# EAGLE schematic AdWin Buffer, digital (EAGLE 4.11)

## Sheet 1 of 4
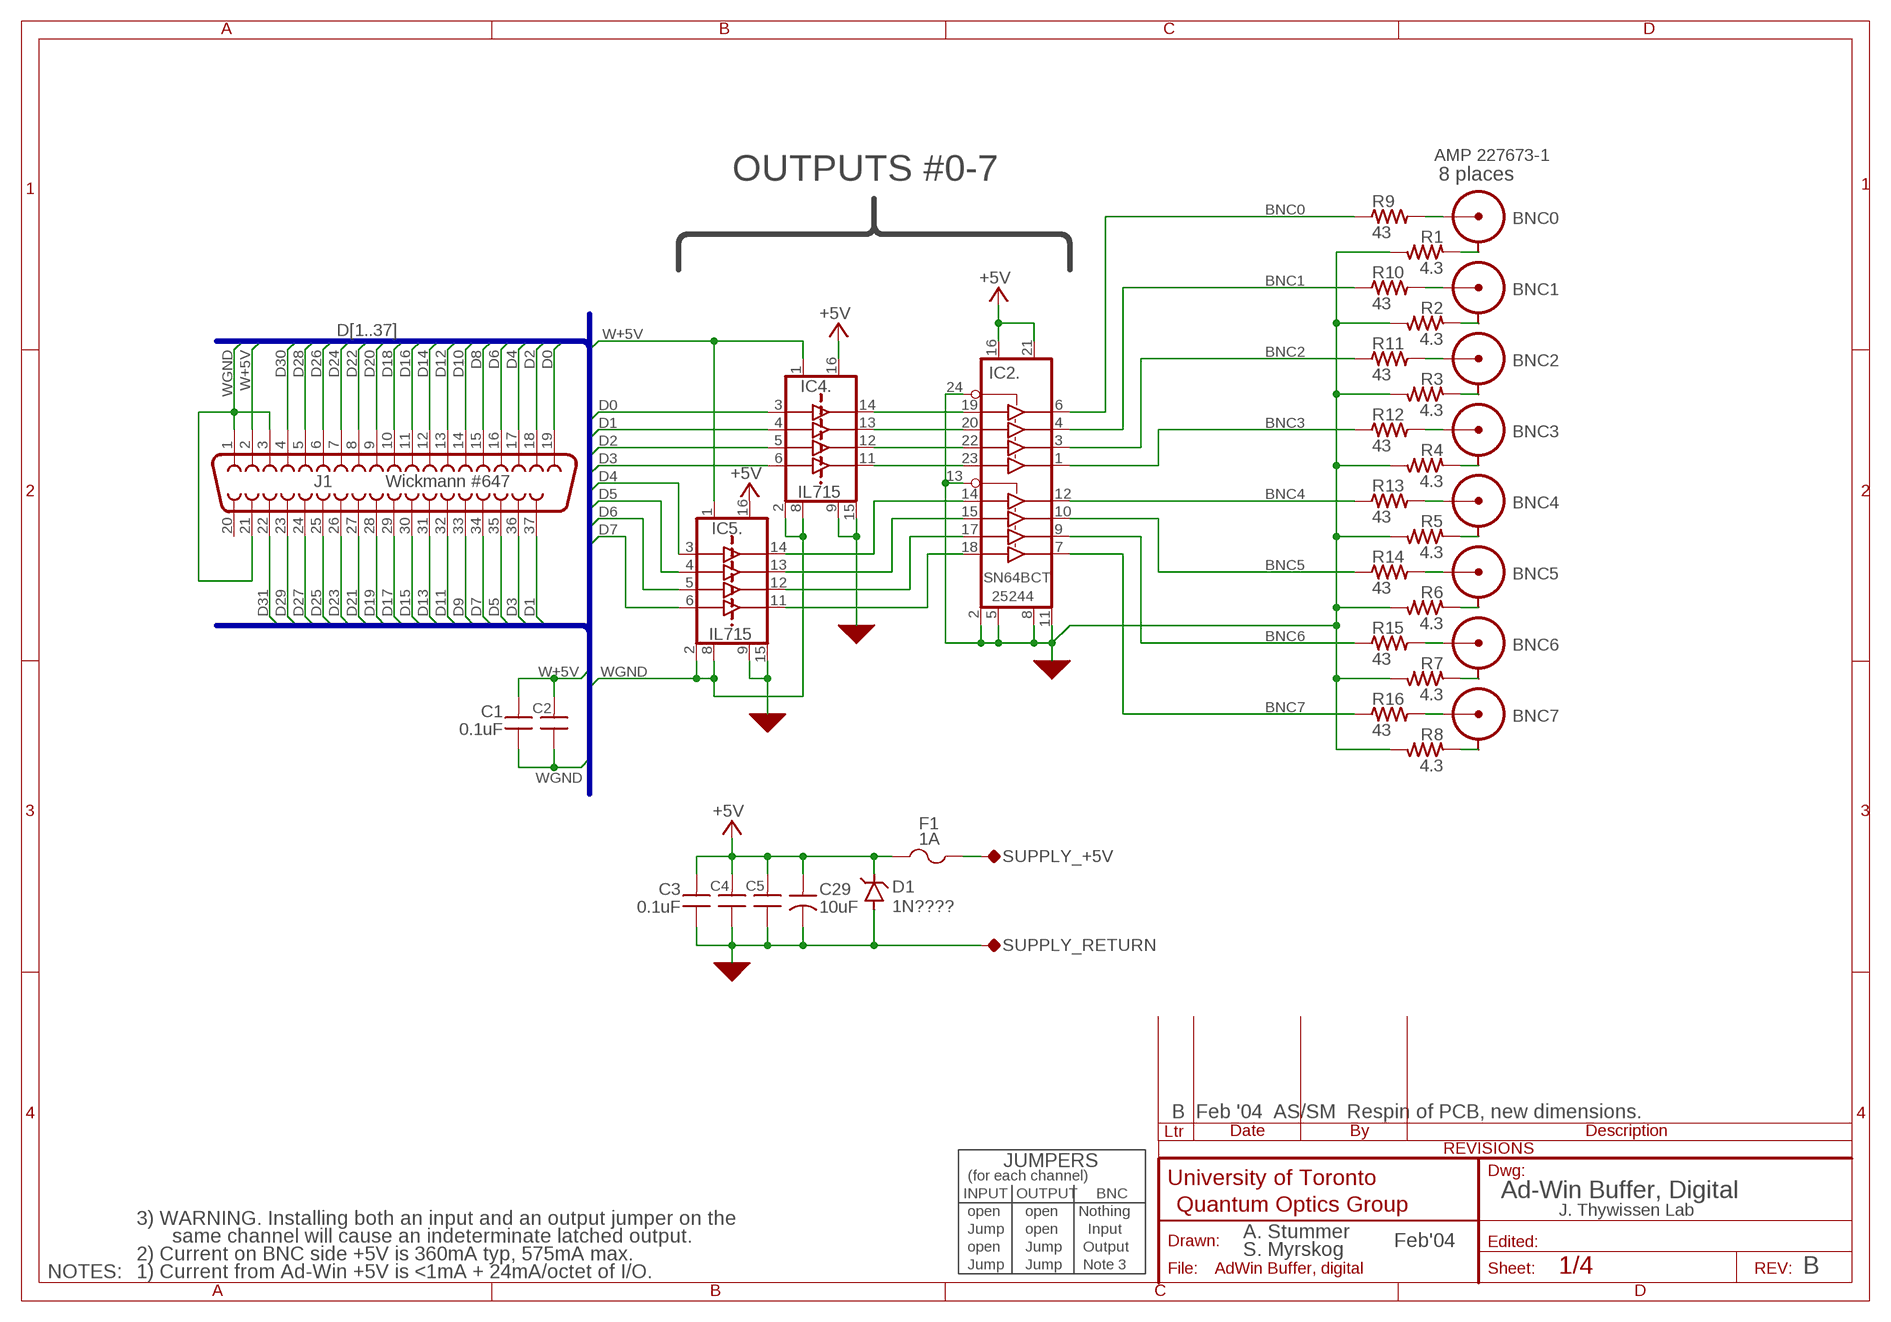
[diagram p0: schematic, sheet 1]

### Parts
BNC0  AMP 227673-1  CONN-BNC-AMPHENOL-PCB-TYPE1  [CONN-BNC-AMPHENOL-TYPE1]
BNC1  CONN-BNC-AMPHENOL-PCB-TYPE1  [CONN-BNC-AMPHENOL-TYPE1]
BNC2  CONN-BNC-AMPHENOL-PCB-TYPE1  [CONN-BNC-AMPHENOL-TYPE1]
BNC3  CONN-BNC-AMPHENOL-PCB-TYPE1  [CONN-BNC-AMPHENOL-TYPE1]
BNC4  CONN-BNC-AMPHENOL-PCB-TYPE1  [CONN-BNC-AMPHENOL-TYPE1]
BNC5  CONN-BNC-AMPHENOL-PCB-TYPE1  [CONN-BNC-AMPHENOL-TYPE1]
BNC6  CONN-BNC-AMPHENOL-PCB-TYPE1  [CONN-BNC-AMPHENOL-TYPE1]
BNC7  CONN-BNC-AMPHENOL-PCB-TYPE1  [CONN-BNC-AMPHENOL-TYPE1]
C1  0.1uF  CAP-V-0805  [0805]
C2  CAP-V-0805  [0805]
C3  0.1uF  CAP-V-0805  [0805]
C4  CAP-V-0805  [0805]
C5  CAP-V-0805  [0805]
C29  10uF  CAP-POL-EIA-B  [EIA-B]
D1  1N????  ZENER-EIA-B  [EIA-B]
F1  1A  FUSE5X20-2  [FUSE5X20-2]
IC2  64BCT25244NT  [DIL24]
IC4  IL715  [SOIC-16]
IC5  IL715  [SOIC-16]
J1  Wickmann #647  CONN-DB37V  [F37V]
R1  4.3  R-H-0805  [0805]
R2  4.3  R-H-0805  [0805]
R3  4.3  R-H-0805  [0805]
R4  4.3  R-H-0805  [0805]
R5  4.3  R-H-0805  [0805]
R6  4.3  R-H-0805  [0805]
R7  4.3  R-H-0805  [0805]
R8  4.3  R-H-0805  [0805]
R9  43  R-H-0805  [0805]
R10  43  R-H-0805  [0805]
R11  43  R-H-0805  [0805]
R12  43  R-H-0805  [0805]
R13  43  R-H-0805  [0805]
R14  43  R-H-0805  [0805]
R15  43  R-H-0805  [0805]
R16  43  R-H-0805  [0805]
SUPPLY_+5V  TP-HOLE-0.042  [TP-HOLE]
SUPPLY_RETURN  TP-HOLE-0.042  [TP-HOLE]

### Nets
+5V [Pwr/Gnd .025"w]: C3.2 C4.2 C5.2 C29.2(POS) D1.2(C) F1.1(1A) IC2.16(.:VDD1) IC2.21(.:VDD2) IC4.16(.:VDDOUT) IC5.16(.:VDDOUT) ; also sheet 2,3,4
AGND [Pwr/Gnd .025"w]: C3.1 C4.1 C5.1 C29.1(NEG) D1.1(A) IC2.2(.:COM1) IC2.5(.:COM2) IC2.8(.:COM3) IC2.11(.:COM4) IC2.13(.:EN-58) IC2.24(.:EN-14) IC4.9(.:COM1OUT) IC4.15(.:COM2OUT) IC5.9(.:COM1OUT) IC5.15(.:COM2OUT) R1.2 R2.2 R3.2 R4.2 R5.2 R6.2 R7.2 R8.2 SUPPLY_RETURN.P$1(TP) ; also sheet 2,3,4
BNC0: IC2.6(4:Q) R9.1
BNC1: IC2.4(3:Q) R10.1
BNC2: IC2.3(2:Q) R11.1
BNC3: IC2.1(1:Q) R12.1
BNC4: IC2.12(8:Q) R13.1
BNC5: IC2.10(7:Q) R14.1
BNC6: IC2.9(6:Q) R15.1
BNC7: IC2.7(5:Q) R16.1
D0: IC4.3(IN) J1.19
D1: IC4.4(IN) J1.37
D2: IC4.5(IN) J1.18
D3: IC4.6(IN) J1.36
D4: IC5.3(IN) J1.17
D5: IC5.4(IN) J1.35
D6: IC5.5(IN) J1.16
D7: IC5.6(IN) J1.34
D8: J1.15 ; also sheet 2
D9: J1.33 ; also sheet 2
D10: J1.14 ; also sheet 2
D11: J1.32 ; also sheet 2
D12: J1.13 ; also sheet 2
D13: J1.31 ; also sheet 2
D14: J1.12 ; also sheet 2
D15: J1.30 ; also sheet 2
D16: J1.11 ; also sheet 3
D17: J1.29 ; also sheet 3
D18: J1.10 ; also sheet 3
D19: J1.28 ; also sheet 3
D20: J1.9 ; also sheet 3
D21: J1.27 ; also sheet 3
D22: J1.8 ; also sheet 3
D23: J1.26 ; also sheet 3
D24: J1.7 ; also sheet 4
D25: J1.25 ; also sheet 4
D26: J1.6 ; also sheet 4
D27: J1.24 ; also sheet 4
D28: J1.5 ; also sheet 4
D29: J1.23 ; also sheet 4
D30: J1.4 ; also sheet 4
D31: J1.22 ; also sheet 4
N$1: IC2.19(4:IN) IC4.14(Q)
N$2: IC2.20(3:IN) IC4.13(Q)
N$3: IC2.22(2:IN) IC4.12(Q)
N$4: IC2.23(1:IN) IC4.11(Q)
N$7: IC2.18(5:IN) IC5.11(Q)
N$10: BNC0.CONDUCTOR R9.2
N$11: BNC1.CONDUCTOR R10.2
N$12: BNC2.CONDUCTOR R11.2
N$13: BNC3.CONDUCTOR R12.2
N$14: BNC4.CONDUCTOR R13.2
N$15: BNC5.CONDUCTOR R14.2
N$16: IC2.17(6:IN) IC5.12(Q)
N$17: IC2.15(7:IN) IC5.13(Q)
N$18: IC2.14(8:IN) IC5.14(Q)
N$19: BNC6.CONDUCTOR R15.2
N$20: BNC7.CONDUCTOR R16.2
N$24: BNC0.SHIELD R1.1
N$27: BNC1.SHIELD R2.1
N$28: BNC2.SHIELD R3.1
N$29: BNC3.SHIELD R4.1
N$37: BNC4.SHIELD R5.1
N$39: BNC5.SHIELD R6.1
N$40: BNC6.SHIELD R7.1
N$41: BNC7.SHIELD R8.1
N$49 [Pwr/Gnd .025"w]: F1.2(2A) SUPPLY_+5V.P$1(TP)
W+5V [Pwr/Gnd .025"w]: C1.2 C2.2 IC4.1(.:VDDIN) IC5.1(.:VDDIN) J1.2 ; also sheet 2,3,4
WGND [Pwr/Gnd .025"w]: C1.1 C2.1 IC4.2(.:COM1IN) IC4.8(.:COM2IN) IC5.2(.:COM1IN) IC5.8(.:COM2IN) J1.1 J1.3 J1.21 ; also sheet 2,3,4
Unconnected: J1.20

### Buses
D[1..37]

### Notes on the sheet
- OUTPUTS #0-7 | 8 places
- B  Feb '04  AS/SM  Respin of PCB, new dimensions.
- JUMPERS
- (for each channel)
- INPUT | OUTPUT | BNC | Ad-Win Buffer, Digital
- open | open | Nothing | J. Thywissen Lab
- 3) WARNING. Installing both an input and an output jumper on the
- Jump | open | Input
- same channel will cause an indeterminate latched output. | A. Stummer
- Feb'04
- open | Jump | Output
- 2) Current on BNC side +5V is 360mA typ, 575mA max. | S. Myrskog
- Jump | Jump | Note 3
- NOTES: | 1) Current from Ad-Win +5V is <1mA + 24mA/octet of I/O. | B

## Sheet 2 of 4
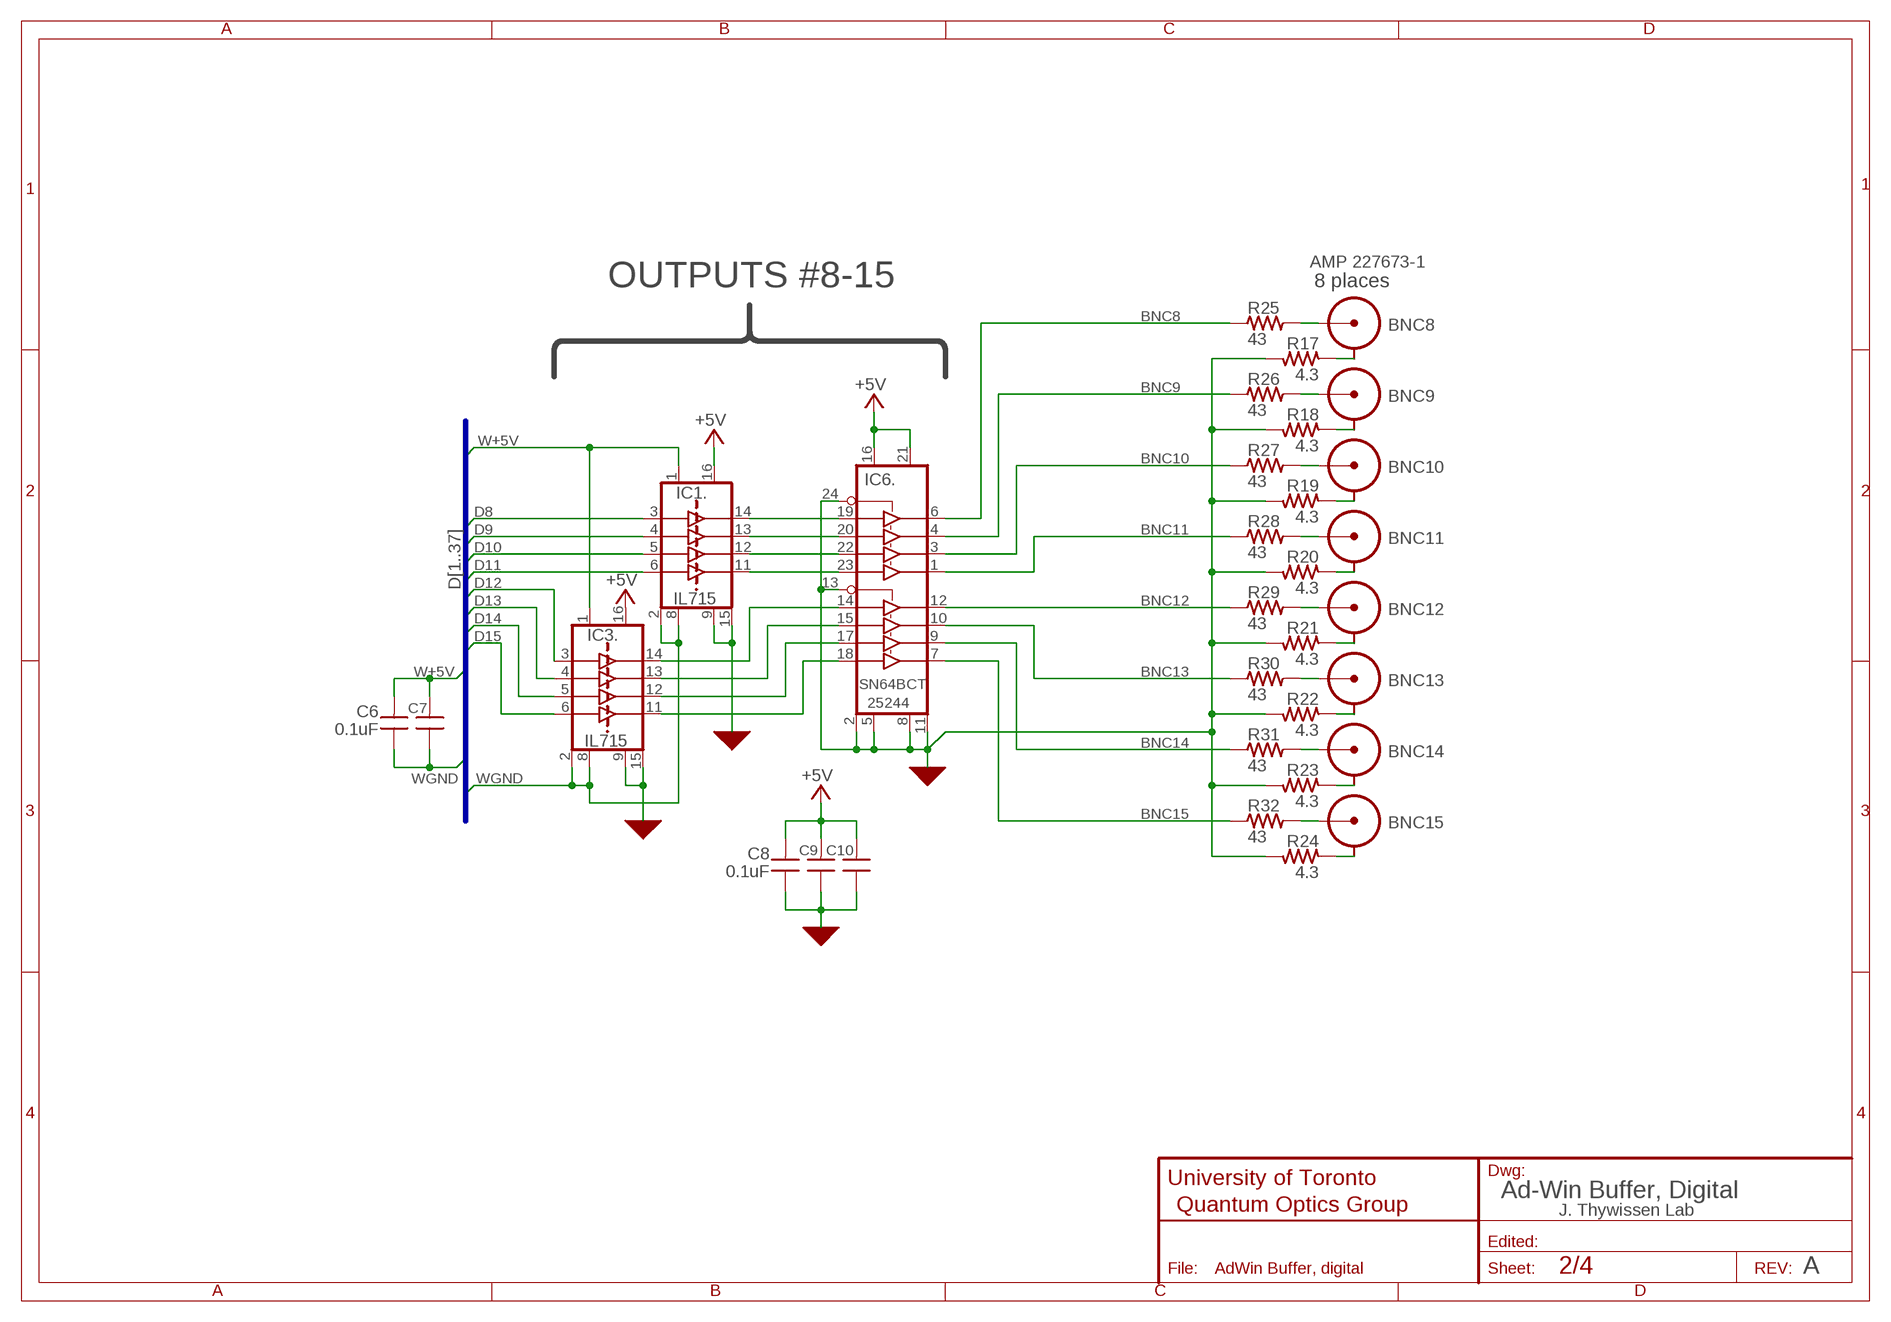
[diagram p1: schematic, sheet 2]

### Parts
BNC8  AMP 227673-1  CONN-BNC-AMPHENOL-PCB-TYPE1  [CONN-BNC-AMPHENOL-TYPE1]
BNC9  CONN-BNC-AMPHENOL-PCB-TYPE1  [CONN-BNC-AMPHENOL-TYPE1]
BNC10  CONN-BNC-AMPHENOL-PCB-TYPE1  [CONN-BNC-AMPHENOL-TYPE1]
BNC11  CONN-BNC-AMPHENOL-PCB-TYPE1  [CONN-BNC-AMPHENOL-TYPE1]
BNC12  CONN-BNC-AMPHENOL-PCB-TYPE1  [CONN-BNC-AMPHENOL-TYPE1]
BNC13  CONN-BNC-AMPHENOL-PCB-TYPE1  [CONN-BNC-AMPHENOL-TYPE1]
BNC14  CONN-BNC-AMPHENOL-PCB-TYPE1  [CONN-BNC-AMPHENOL-TYPE1]
BNC15  CONN-BNC-AMPHENOL-PCB-TYPE1  [CONN-BNC-AMPHENOL-TYPE1]
C6  0.1uF  CAP-V-0805  [0805]
C7  CAP-V-0805  [0805]
C8  0.1uF  CAP-V-0805  [0805]
C9  CAP-V-0805  [0805]
C10  CAP-V-0805  [0805]
IC1  IL715  [SOIC-16]
IC3  IL715  [SOIC-16]
IC6  64BCT25244NT  [DIL24]
R17  4.3  R-H-0805  [0805]
R18  4.3  R-H-0805  [0805]
R19  4.3  R-H-0805  [0805]
R20  4.3  R-H-0805  [0805]
R21  4.3  R-H-0805  [0805]
R22  4.3  R-H-0805  [0805]
R23  4.3  R-H-0805  [0805]
R24  4.3  R-H-0805  [0805]
R25  43  R-H-0805  [0805]
R26  43  R-H-0805  [0805]
R27  43  R-H-0805  [0805]
R28  43  R-H-0805  [0805]
R29  43  R-H-0805  [0805]
R30  43  R-H-0805  [0805]
R31  43  R-H-0805  [0805]
R32  43  R-H-0805  [0805]

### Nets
+5V [Pwr/Gnd .025"w]: C8.2 C9.2 C10.2 IC1.16(.:VDDOUT) IC3.16(.:VDDOUT) IC6.16(.:VDD1) IC6.21(.:VDD2) ; also sheet 1,3,4
AGND [Pwr/Gnd .025"w]: C8.1 C9.1 C10.1 IC1.9(.:COM1OUT) IC1.15(.:COM2OUT) IC3.9(.:COM1OUT) IC3.15(.:COM2OUT) IC6.2(.:COM1) IC6.5(.:COM2) IC6.8(.:COM3) IC6.11(.:COM4) IC6.13(.:EN-58) IC6.24(.:EN-14) R17.2 R18.2 R19.2 R20.2 R21.2 R22.2 R23.2 R24.2 ; also sheet 1,3,4
BNC8: IC6.6(4:Q) R25.1
BNC9: IC6.4(3:Q) R26.1
BNC10: IC6.3(2:Q) R27.1
BNC11: IC6.1(1:Q) R28.1
BNC12: IC6.12(8:Q) R29.1
BNC13: IC6.10(7:Q) R30.1
BNC14: IC6.9(6:Q) R31.1
BNC15: IC6.7(5:Q) R32.1
D8: IC1.3(IN) ; also sheet 1
D9: IC1.4(IN) ; also sheet 1
D10: IC1.5(IN) ; also sheet 1
D11: IC1.6(IN) ; also sheet 1
D12: IC3.3(IN) ; also sheet 1
D13: IC3.4(IN) ; also sheet 1
D14: IC3.5(IN) ; also sheet 1
D15: IC3.6(IN) ; also sheet 1
N$5: IC1.14(Q) IC6.19(4:IN)
N$6: IC1.13(Q) IC6.20(3:IN)
N$8: IC1.12(Q) IC6.22(2:IN)
N$9: IC1.11(Q) IC6.23(1:IN)
N$21: IC3.11(Q) IC6.18(5:IN)
N$22: IC3.12(Q) IC6.17(6:IN)
N$23: IC3.13(Q) IC6.15(7:IN)
N$25: IC3.14(Q) IC6.14(8:IN)
N$26: BNC8.SHIELD R17.1
N$30: BNC9.SHIELD R18.1
N$31: BNC10.SHIELD R19.1
N$32: BNC11.SHIELD R20.1
N$33: BNC12.SHIELD R21.1
N$34: BNC13.SHIELD R22.1
N$35: BNC14.SHIELD R23.1
N$36: BNC15.SHIELD R24.1
N$38: BNC8.CONDUCTOR R25.2
N$42: BNC9.CONDUCTOR R26.2
N$43: BNC10.CONDUCTOR R27.2
N$44: BNC11.CONDUCTOR R28.2
N$45: BNC12.CONDUCTOR R29.2
N$46: BNC13.CONDUCTOR R30.2
N$47: BNC14.CONDUCTOR R31.2
N$48: BNC15.CONDUCTOR R32.2
W+5V [Pwr/Gnd .025"w]: C6.2 C7.2 IC1.1(.:VDDIN) IC3.1(.:VDDIN) ; also sheet 1,3,4
WGND [Pwr/Gnd .025"w]: C6.1 C7.1 IC1.2(.:COM1IN) IC1.8(.:COM2IN) IC3.2(.:COM1IN) IC3.8(.:COM2IN) ; also sheet 1,3,4

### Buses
D[1..37]

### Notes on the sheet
- OUTPUTS #8-15 | 8 places
- Ad-Win Buffer, Digital
- J. Thywissen Lab
- A

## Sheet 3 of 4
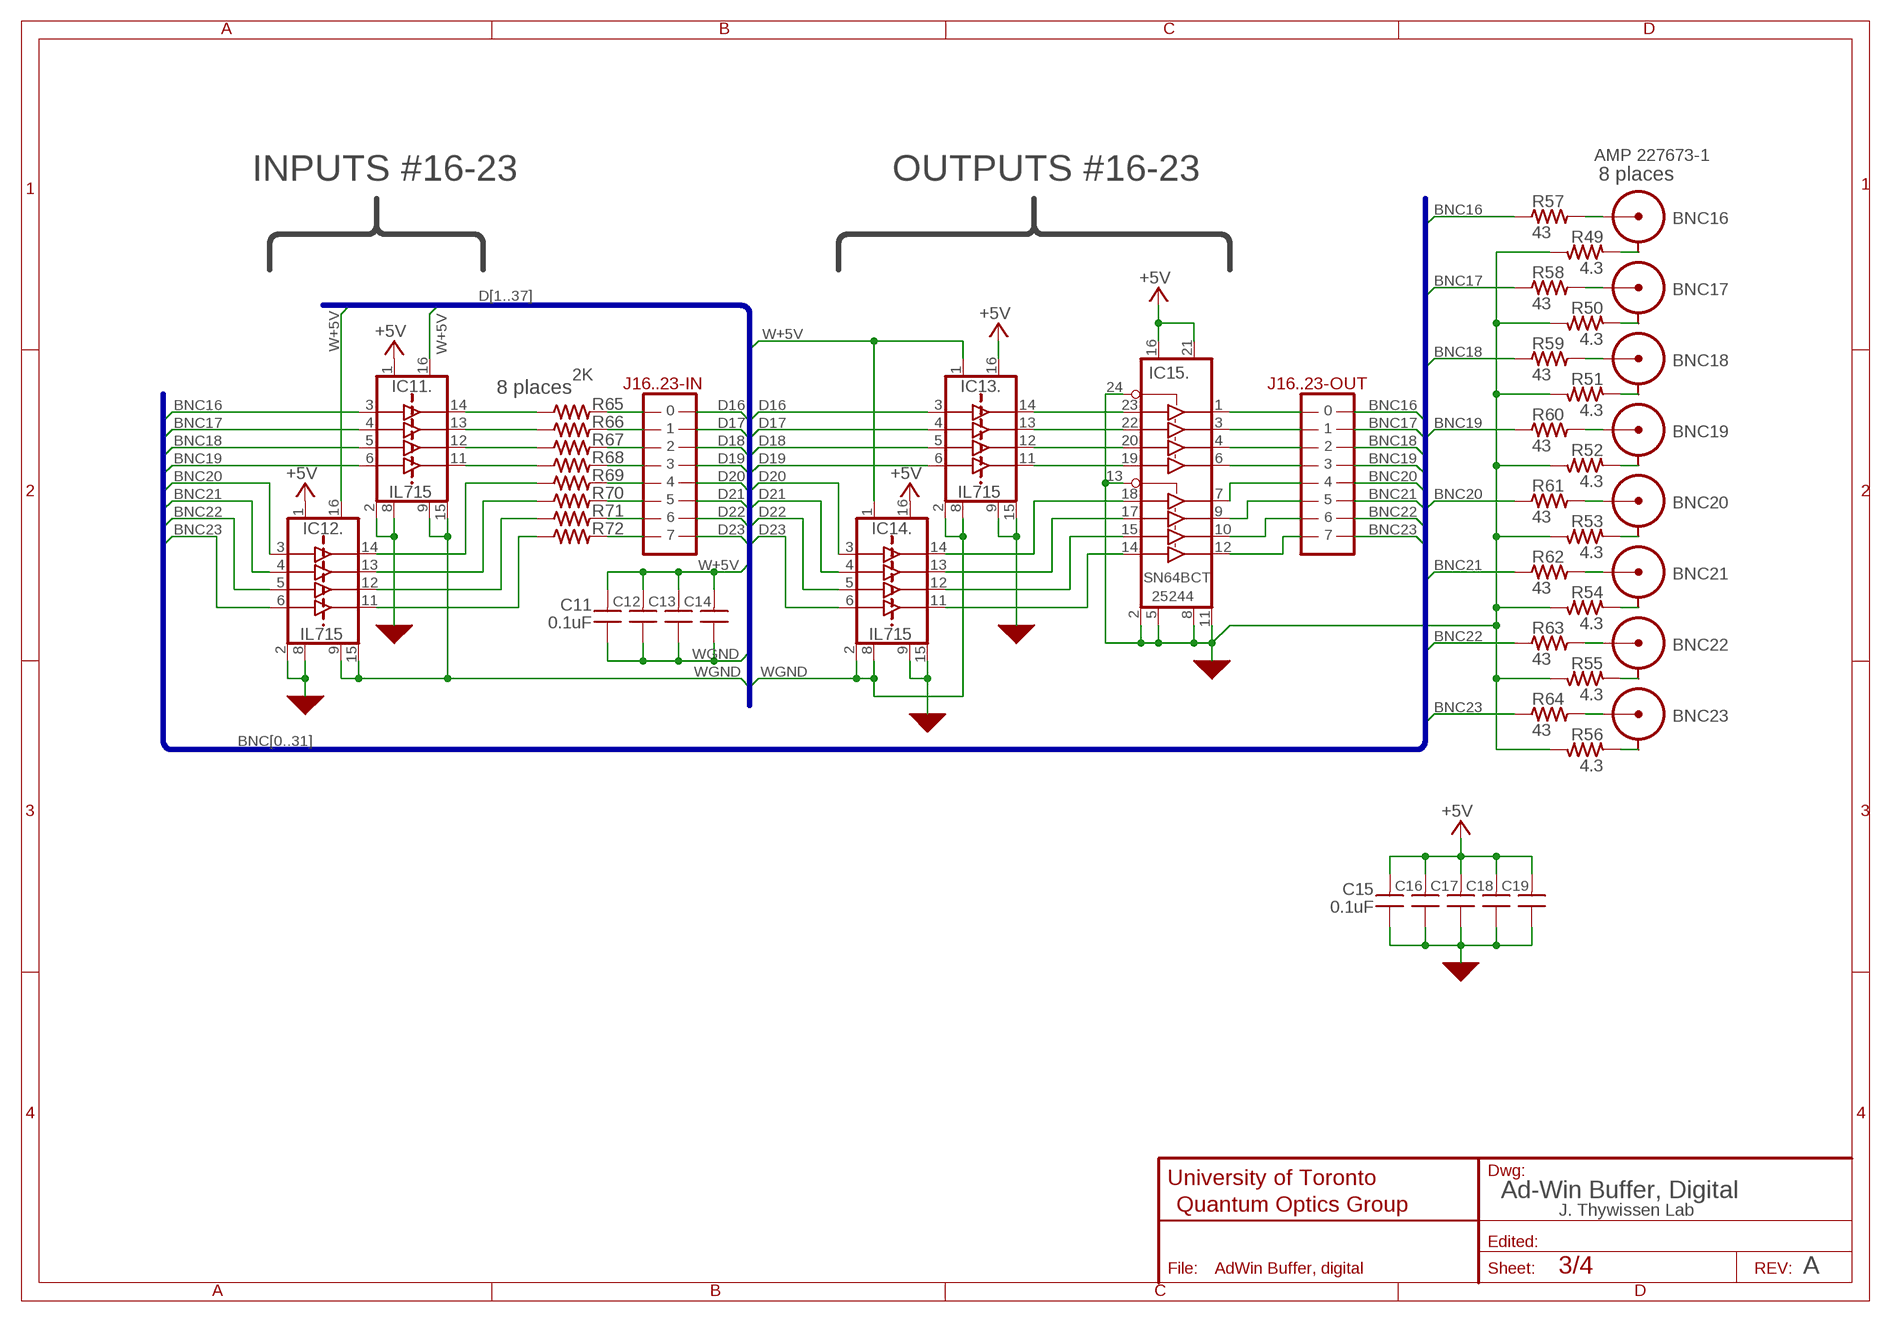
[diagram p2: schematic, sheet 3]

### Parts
BNC16  AMP 227673-1  CONN-BNC-AMPHENOL-PCB-TYPE1  [CONN-BNC-AMPHENOL-TYPE1]
BNC17  CONN-BNC-AMPHENOL-PCB-TYPE1  [CONN-BNC-AMPHENOL-TYPE1]
BNC18  CONN-BNC-AMPHENOL-PCB-TYPE1  [CONN-BNC-AMPHENOL-TYPE1]
BNC19  CONN-BNC-AMPHENOL-PCB-TYPE1  [CONN-BNC-AMPHENOL-TYPE1]
BNC20  CONN-BNC-AMPHENOL-PCB-TYPE1  [CONN-BNC-AMPHENOL-TYPE1]
BNC21  CONN-BNC-AMPHENOL-PCB-TYPE1  [CONN-BNC-AMPHENOL-TYPE1]
BNC22  CONN-BNC-AMPHENOL-PCB-TYPE1  [CONN-BNC-AMPHENOL-TYPE1]
BNC23  CONN-BNC-AMPHENOL-PCB-TYPE1  [CONN-BNC-AMPHENOL-TYPE1]
C11  0.1uF  CAP-V-0805  [0805]
C12  CAP-V-0805  [0805]
C13  CAP-V-0805  [0805]
C14  CAP-V-0805  [0805]
C15  0.1uF  CAP-V-0805  [0805]
C16  CAP-V-0805  [0805]
C17  CAP-V-0805  [0805]
C18  CAP-V-0805  [0805]
C19  CAP-V-0805  [0805]
IC11  IL715  [SOIC-16]
IC12  IL715  [SOIC-16]
IC13  IL715  [SOIC-16]
IC14  IL715  [SOIC-16]
IC15  64BCT25244NT  [DIL24]
J16..23-IN  JUMPER-2X8  [JUMPER-2X8]
J16..23-OUT  JUMPER-2X8  [JUMPER-2X8]
R49  4.3  R-H-0805  [0805]
R50  4.3  R-H-0805  [0805]
R51  4.3  R-H-0805  [0805]
R52  4.3  R-H-0805  [0805]
R53  4.3  R-H-0805  [0805]
R54  4.3  R-H-0805  [0805]
R55  4.3  R-H-0805  [0805]
R56  4.3  R-H-0805  [0805]
R57  43  R-H-0805  [0805]
R58  43  R-H-0805  [0805]
R59  43  R-H-0805  [0805]
R60  43  R-H-0805  [0805]
R61  43  R-H-0805  [0805]
R62  43  R-H-0805  [0805]
R63  43  R-H-0805  [0805]
R64  43  R-H-0805  [0805]
R65  2K  R-H-0805  [0805]
R66  R-H-0805  [0805]
R67  R-H-0805  [0805]
R68  R-H-0805  [0805]
R69  R-H-0805  [0805]
R70  R-H-0805  [0805]
R71  R-H-0805  [0805]
R72  R-H-0805  [0805]

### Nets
+5V [Pwr/Gnd .025"w]: C15.2 C16.2 C17.2 C18.2 C19.2 IC11.1(.:VDDIN) IC12.1(.:VDDIN) IC13.16(.:VDDOUT) IC14.16(.:VDDOUT) IC15.16(.:VDD1) IC15.21(.:VDD2) ; also sheet 1,2,4
AGND [Pwr/Gnd .025"w]: C15.1 C16.1 C17.1 C18.1 C19.1 IC11.2(.:COM1IN) IC11.8(.:COM2IN) IC12.2(.:COM1IN) IC12.8(.:COM2IN) IC13.9(.:COM1OUT) IC13.15(.:COM2OUT) IC14.9(.:COM1OUT) IC14.15(.:COM2OUT) IC15.2(.:COM1) IC15.5(.:COM2) IC15.8(.:COM3) IC15.11(.:COM4) IC15.13(.:EN-58) IC15.24(.:EN-14) R49.2 R50.2 R51.2 R52.2 R53.2 R54.2 R55.2 R56.2 ; also sheet 1,2,4
BNC16: IC11.3(IN) J16..23-OUT.9 R57.1
BNC17: IC11.4(IN) J16..23-OUT.10 R58.1
BNC18: IC11.5(IN) J16..23-OUT.11 R59.1
BNC19: IC11.6(IN) J16..23-OUT.12 R60.1
BNC20: IC12.3(IN) J16..23-OUT.13 R61.1
BNC21: IC12.4(IN) J16..23-OUT.14 R62.1
BNC22: IC12.5(IN) J16..23-OUT.15 R63.1
BNC23: IC12.6(IN) J16..23-OUT.16 R64.1
D16: IC13.3(IN) J16..23-IN.9 ; also sheet 1
D17: IC13.4(IN) J16..23-IN.10 ; also sheet 1
D18: IC13.5(IN) J16..23-IN.11 ; also sheet 1
D19: IC13.6(IN) J16..23-IN.12 ; also sheet 1
D20: IC14.3(IN) J16..23-IN.13 ; also sheet 1
D21: IC14.4(IN) J16..23-IN.14 ; also sheet 1
D22: IC14.5(IN) J16..23-IN.15 ; also sheet 1
D23: IC14.6(IN) J16..23-IN.16 ; also sheet 1
N$97: IC13.14(Q) IC15.23(1:IN)
N$98: IC13.13(Q) IC15.22(2:IN)
N$99: IC13.12(Q) IC15.20(3:IN)
N$100: IC13.11(Q) IC15.19(4:IN)
N$101: IC14.11(Q) IC15.14(8:IN)
N$102: IC14.12(Q) IC15.15(7:IN)
N$103: IC14.13(Q) IC15.17(6:IN)
N$104: IC14.14(Q) IC15.18(5:IN)
N$105: IC12.11(Q) R72.1
N$106: IC12.12(Q) R71.1
N$107: IC12.13(Q) R70.1
N$108: IC12.14(Q) R69.1
N$109: IC15.12(8:Q) J16..23-OUT.8
N$110: IC15.10(7:Q) J16..23-OUT.7
N$111: IC15.9(6:Q) J16..23-OUT.6
N$112: IC15.7(5:Q) J16..23-OUT.5
N$113: BNC16.SHIELD R49.1
N$114: BNC17.SHIELD R50.1
N$115: BNC18.SHIELD R51.1
N$116: BNC19.SHIELD R52.1
N$117: BNC20.SHIELD R53.1
N$118: BNC21.SHIELD R54.1
N$119: BNC22.SHIELD R55.1
N$120: BNC23.SHIELD R56.1
N$121: IC15.1(1:Q) J16..23-OUT.1
N$122: IC15.3(2:Q) J16..23-OUT.2
N$123: IC15.4(3:Q) J16..23-OUT.3
N$124: IC15.6(4:Q) J16..23-OUT.4
N$125: BNC16.CONDUCTOR R57.2
N$126: BNC17.CONDUCTOR R58.2
N$127: BNC18.CONDUCTOR R59.2
N$128: BNC19.CONDUCTOR R60.2
N$129: BNC20.CONDUCTOR R61.2
N$130: BNC21.CONDUCTOR R62.2
N$131: BNC22.CONDUCTOR R63.2
N$132: BNC23.CONDUCTOR R64.2
N$133: J16..23-IN.1 R65.2
N$134: J16..23-IN.2 R66.2
N$135: J16..23-IN.3 R67.2
N$136: J16..23-IN.4 R68.2
N$137: J16..23-IN.5 R69.2
N$138: J16..23-IN.6 R70.2
N$139: J16..23-IN.7 R71.2
N$140: J16..23-IN.8 R72.2
N$141: IC11.14(Q) R65.1
N$142: IC11.13(Q) R66.1
N$143: IC11.12(Q) R67.1
N$144: IC11.11(Q) R68.1
W+5V [Pwr/Gnd .025"w]: C11.2 C12.2 C13.2 C14.2 IC11.16(.:VDDOUT) IC12.16(.:VDDOUT) IC13.1(.:VDDIN) IC14.1(.:VDDIN) ; also sheet 1,2,4
WGND [Pwr/Gnd .025"w]: C11.1 C12.1 C13.1 C14.1 IC11.9(.:COM1OUT) IC11.15(.:COM2OUT) IC12.9(.:COM1OUT) IC12.15(.:COM2OUT) IC13.2(.:COM1IN) IC13.8(.:COM2IN) IC14.2(.:COM1IN) IC14.8(.:COM2IN) ; also sheet 1,2,4

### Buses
D[1..37]
BNC[0..31]

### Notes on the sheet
- INPUTS #16-23 | OUTPUTS #16-23 | 8 places
- 8 places
- 0 | 0
- 1 | 1
- 2 | 2
- 3 | 3
- 4 | 4
- 5 | 5
- 6 | 6
- 7 | 7
- Ad-Win Buffer, Digital
- J. Thywissen Lab
- A

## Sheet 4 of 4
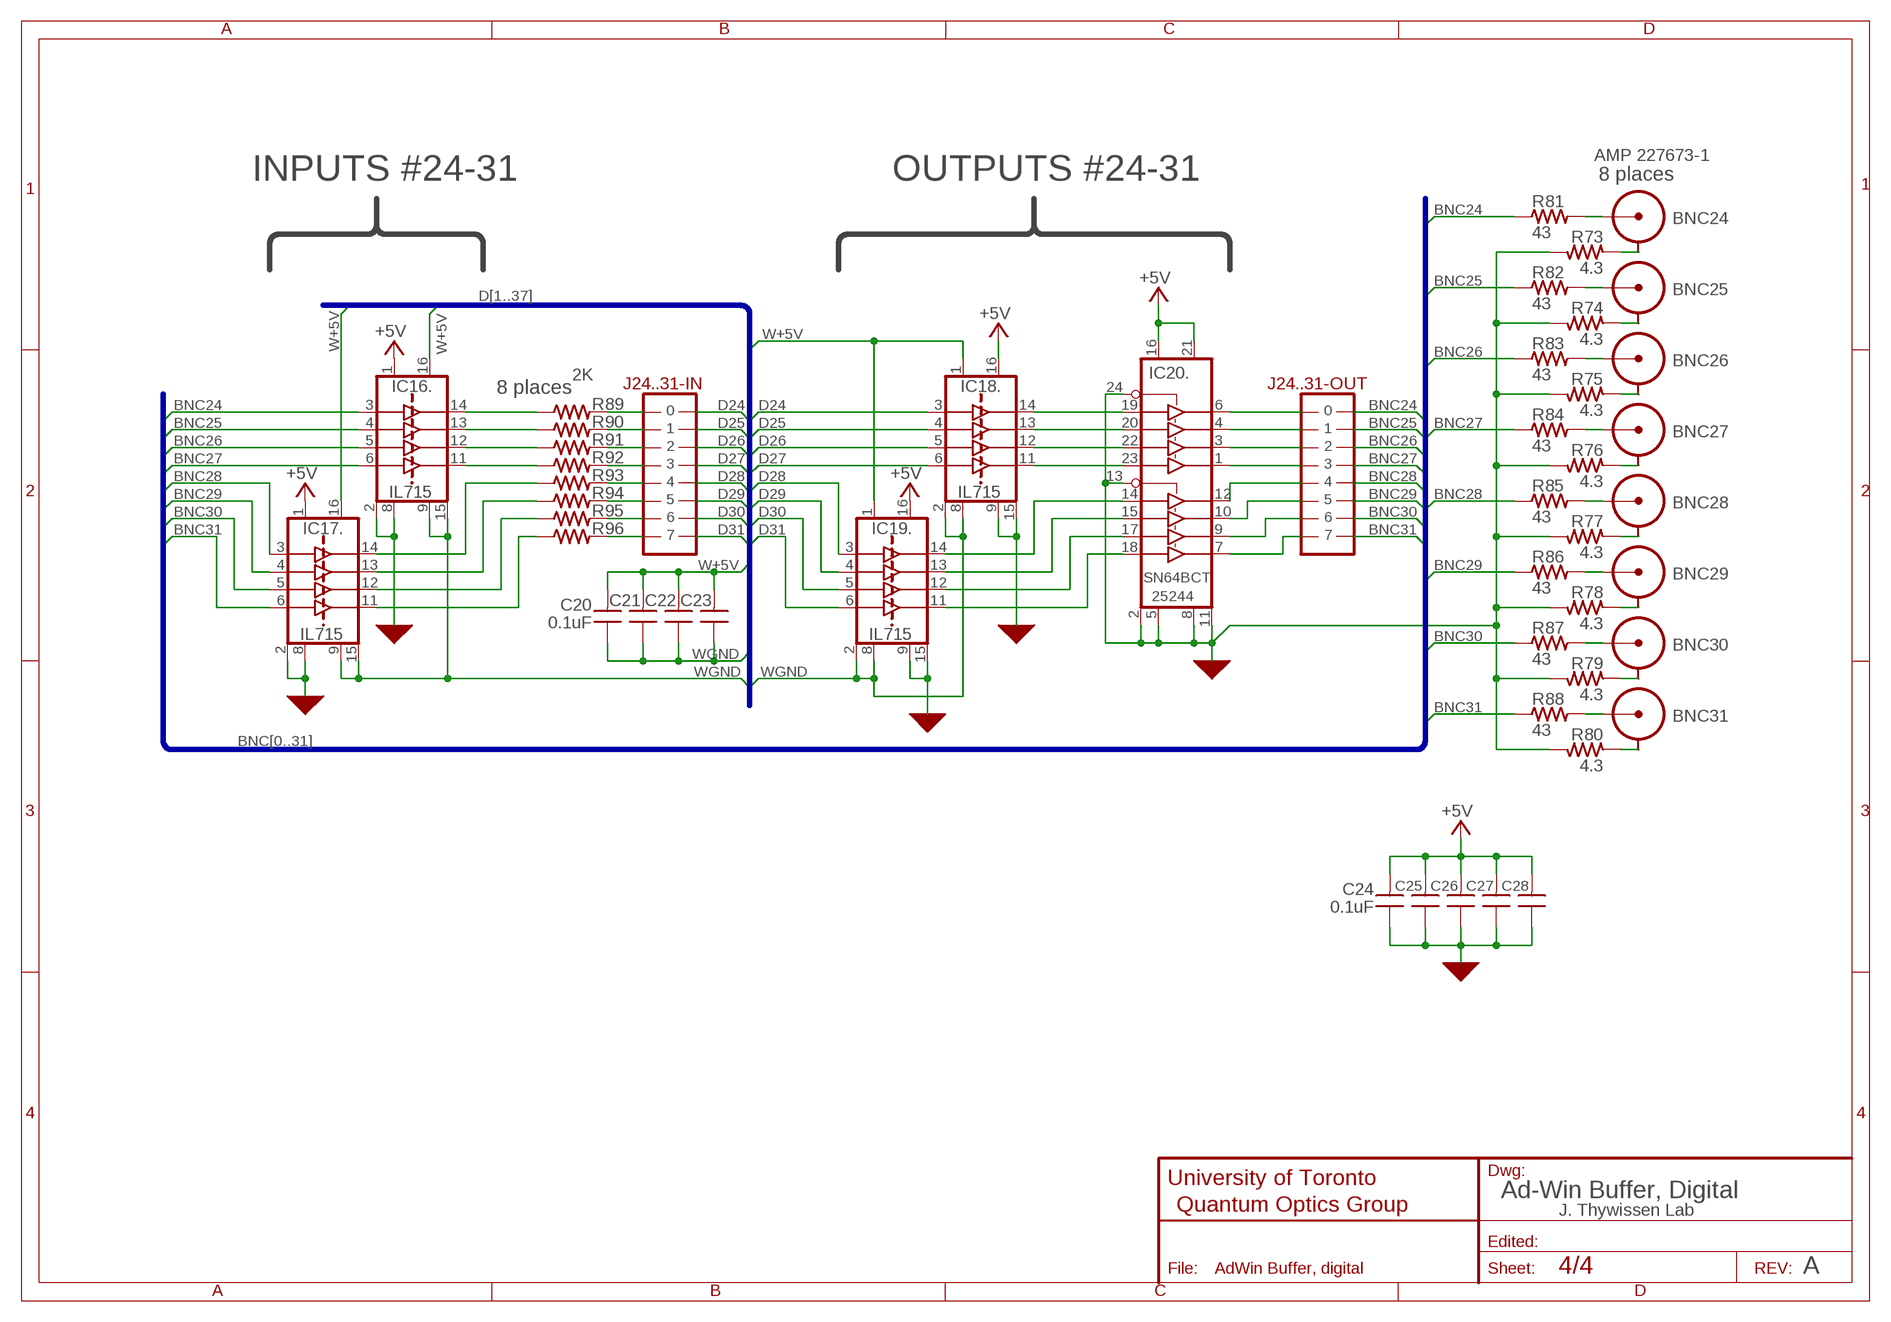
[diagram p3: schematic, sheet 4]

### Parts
BNC24  AMP 227673-1  CONN-BNC-AMPHENOL-PCB-TYPE1  [CONN-BNC-AMPHENOL-TYPE1]
BNC25  CONN-BNC-AMPHENOL-PCB-TYPE1  [CONN-BNC-AMPHENOL-TYPE1]
BNC26  CONN-BNC-AMPHENOL-PCB-TYPE1  [CONN-BNC-AMPHENOL-TYPE1]
BNC27  CONN-BNC-AMPHENOL-PCB-TYPE1  [CONN-BNC-AMPHENOL-TYPE1]
BNC28  CONN-BNC-AMPHENOL-PCB-TYPE1  [CONN-BNC-AMPHENOL-TYPE1]
BNC29  CONN-BNC-AMPHENOL-PCB-TYPE1  [CONN-BNC-AMPHENOL-TYPE1]
BNC30  CONN-BNC-AMPHENOL-PCB-TYPE1  [CONN-BNC-AMPHENOL-TYPE1]
BNC31  CONN-BNC-AMPHENOL-PCB-TYPE1  [CONN-BNC-AMPHENOL-TYPE1]
C20  0.1uF  CAP-V-0805  [0805]
C21  CAP-V-0805  [0805]
C22  CAP-V-0805  [0805]
C23  CAP-V-0805  [0805]
C24  0.1uF  CAP-V-0805  [0805]
C25  CAP-V-0805  [0805]
C26  CAP-V-0805  [0805]
C27  CAP-V-0805  [0805]
C28  CAP-V-0805  [0805]
IC16  IL715  [SOIC-16]
IC17  IL715  [SOIC-16]
IC18  IL715  [SOIC-16]
IC19  IL715  [SOIC-16]
IC20  64BCT25244NT  [DIL24]
J24..31-IN  JUMPER-2X8  [JUMPER-2X8]
J24..31-OUT  JUMPER-2X8  [JUMPER-2X8]
R73  4.3  R-H-0805  [0805]
R74  4.3  R-H-0805  [0805]
R75  4.3  R-H-0805  [0805]
R76  4.3  R-H-0805  [0805]
R77  4.3  R-H-0805  [0805]
R78  4.3  R-H-0805  [0805]
R79  4.3  R-H-0805  [0805]
R80  4.3  R-H-0805  [0805]
R81  43  R-H-0805  [0805]
R82  43  R-H-0805  [0805]
R83  43  R-H-0805  [0805]
R84  43  R-H-0805  [0805]
R85  43  R-H-0805  [0805]
R86  43  R-H-0805  [0805]
R87  43  R-H-0805  [0805]
R88  43  R-H-0805  [0805]
R89  2K  R-H-0805  [0805]
R90  R-H-0805  [0805]
R91  R-H-0805  [0805]
R92  R-H-0805  [0805]
R93  R-H-0805  [0805]
R94  R-H-0805  [0805]
R95  R-H-0805  [0805]
R96  R-H-0805  [0805]

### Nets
+5V [Pwr/Gnd .025"w]: C24.2 C25.2 C26.2 C27.2 C28.2 IC16.1(.:VDDIN) IC17.1(.:VDDIN) IC18.16(.:VDDOUT) IC19.16(.:VDDOUT) IC20.16(.:VDD1) IC20.21(.:VDD2) ; also sheet 1,2,3
AGND [Pwr/Gnd .025"w]: C24.1 C25.1 C26.1 C27.1 C28.1 IC16.2(.:COM1IN) IC16.8(.:COM2IN) IC17.2(.:COM1IN) IC17.8(.:COM2IN) IC18.9(.:COM1OUT) IC18.15(.:COM2OUT) IC19.9(.:COM1OUT) IC19.15(.:COM2OUT) IC20.2(.:COM1) IC20.5(.:COM2) IC20.8(.:COM3) IC20.11(.:COM4) IC20.13(.:EN-58) IC20.24(.:EN-14) R73.2 R74.2 R75.2 R76.2 R77.2 R78.2 R79.2 R80.2 ; also sheet 1,2,3
BNC24: IC16.3(IN) J24..31-OUT.9 R81.1
BNC25: IC16.4(IN) J24..31-OUT.10 R82.1
BNC26: IC16.5(IN) J24..31-OUT.11 R83.1
BNC27: IC16.6(IN) J24..31-OUT.12 R84.1
BNC28: IC17.3(IN) J24..31-OUT.13 R85.1
BNC29: IC17.4(IN) J24..31-OUT.14 R86.1
BNC30: IC17.5(IN) J24..31-OUT.15 R87.1
BNC31: IC17.6(IN) J24..31-OUT.16 R88.1
D24: IC18.3(IN) J24..31-IN.9 ; also sheet 1
D25: IC18.4(IN) J24..31-IN.10 ; also sheet 1
D26: IC18.5(IN) J24..31-IN.11 ; also sheet 1
D27: IC18.6(IN) J24..31-IN.12 ; also sheet 1
D28: IC19.3(IN) J24..31-IN.13 ; also sheet 1
D29: IC19.4(IN) J24..31-IN.14 ; also sheet 1
D30: IC19.5(IN) J24..31-IN.15 ; also sheet 1
D31: IC19.6(IN) J24..31-IN.16 ; also sheet 1
N$145: IC18.14(Q) IC20.19(4:IN)
N$146: IC18.13(Q) IC20.20(3:IN)
N$147: IC18.12(Q) IC20.22(2:IN)
N$148: IC18.11(Q) IC20.23(1:IN)
N$149: IC19.11(Q) IC20.18(5:IN)
N$150: IC19.12(Q) IC20.17(6:IN)
N$151: IC19.13(Q) IC20.15(7:IN)
N$152: IC19.14(Q) IC20.14(8:IN)
N$153: IC17.11(Q) R96.1
N$154: IC17.12(Q) R95.1
N$155: IC17.13(Q) R94.1
N$156: IC17.14(Q) R93.1
N$157: IC20.7(5:Q) J24..31-OUT.8
N$158: IC20.9(6:Q) J24..31-OUT.7
N$159: IC20.10(7:Q) J24..31-OUT.6
N$160: IC20.12(8:Q) J24..31-OUT.5
N$161: BNC24.SHIELD R73.1
N$162: BNC25.SHIELD R74.1
N$163: BNC26.SHIELD R75.1
N$164: BNC27.SHIELD R76.1
N$165: BNC28.SHIELD R77.1
N$166: BNC29.SHIELD R78.1
N$167: BNC30.SHIELD R79.1
N$168: BNC31.SHIELD R80.1
N$169: IC20.6(4:Q) J24..31-OUT.1
N$170: IC20.4(3:Q) J24..31-OUT.2
N$171: IC20.3(2:Q) J24..31-OUT.3
N$172: IC20.1(1:Q) J24..31-OUT.4
N$173: BNC24.CONDUCTOR R81.2
N$174: BNC25.CONDUCTOR R82.2
N$175: BNC26.CONDUCTOR R83.2
N$176: BNC27.CONDUCTOR R84.2
N$177: BNC28.CONDUCTOR R85.2
N$178: BNC29.CONDUCTOR R86.2
N$179: BNC30.CONDUCTOR R87.2
N$180: BNC31.CONDUCTOR R88.2
N$181: J24..31-IN.1 R89.2
N$182: J24..31-IN.2 R90.2
N$183: J24..31-IN.3 R91.2
N$184: J24..31-IN.4 R92.2
N$185: J24..31-IN.5 R93.2
N$186: J24..31-IN.6 R94.2
N$187: J24..31-IN.7 R95.2
N$188: J24..31-IN.8 R96.2
N$189: IC16.14(Q) R89.1
N$190: IC16.13(Q) R90.1
N$191: IC16.12(Q) R91.1
N$192: IC16.11(Q) R92.1
W+5V [Pwr/Gnd .025"w]: C20.2 C21.2 C22.2 C23.2 IC16.16(.:VDDOUT) IC17.16(.:VDDOUT) IC18.1(.:VDDIN) IC19.1(.:VDDIN) ; also sheet 1,2,3
WGND [Pwr/Gnd .025"w]: C20.1 C21.1 C22.1 C23.1 IC16.9(.:COM1OUT) IC16.15(.:COM2OUT) IC17.9(.:COM1OUT) IC17.15(.:COM2OUT) IC18.2(.:COM1IN) IC18.8(.:COM2IN) IC19.2(.:COM1IN) IC19.8(.:COM2IN) ; also sheet 1,2,3

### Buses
D[1..37]
BNC[0..31]

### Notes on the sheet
- INPUTS #24-31 | OUTPUTS #24-31 | 8 places
- 8 places
- 0 | 0
- 1 | 1
- 2 | 2
- 3 | 3
- 4 | 4
- 5 | 5
- 6 | 6
- 7 | 7
- Ad-Win Buffer, Digital
- J. Thywissen Lab
- A

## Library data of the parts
BNC0 BNC1-BNC31 = 0-UofT-Physics:CONN-BNC: BNC connector
C1-C28 = 0-UofT-Physics:CAP-V-: Cap, SMT, 0402 to 1206
C29 = 0-UofT-Physics:CAP-POL-: Capacitor, Polarized, electrolytic (tantalum)l.
D1 = 0-UofT-Physics:ZENER: Zener
F1 = 0-UofT-Physics:FUSE: Fuse
IC1 IC3-IC5 IC11-IC14 IC16-IC19 = 0-UofT-Physics:IL715: IL715 from NVE, quad-TTL isolator. Magnetic isolation.
IC2 IC6 IC15 IC20 = 0-UofT-Physics:64BCT25244: Octal TTL Buffer, tri-state in two groups, high current 50 Ohm driver.
J1 = 0-UofT-Physics:CONN-DB37: D-Type DB-37
J16..23-IN J16..23-OUT J24..31-IN J24..31-OUT = 0-UofT-Physics:JUMPER-2X8: Jumper 2 x 8, 2 x 8 on a 0.1 grid.
R1-R32 R49-R96 = 0-UofT-Physics:R-H-*: Resistor, SMT, horizontal symbol
SUPPLY_+5V SUPPLY_RETURN = 0-UofT-Physics:TP: Testpoint, test point on schematic, small pad on PCB.

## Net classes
1 Pwr/Gnd .016"w: width 0.406 mm
2 Pwr/Gnd .025"w: width 0.635 mm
